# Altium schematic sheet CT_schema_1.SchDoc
size 515 x 464 mm
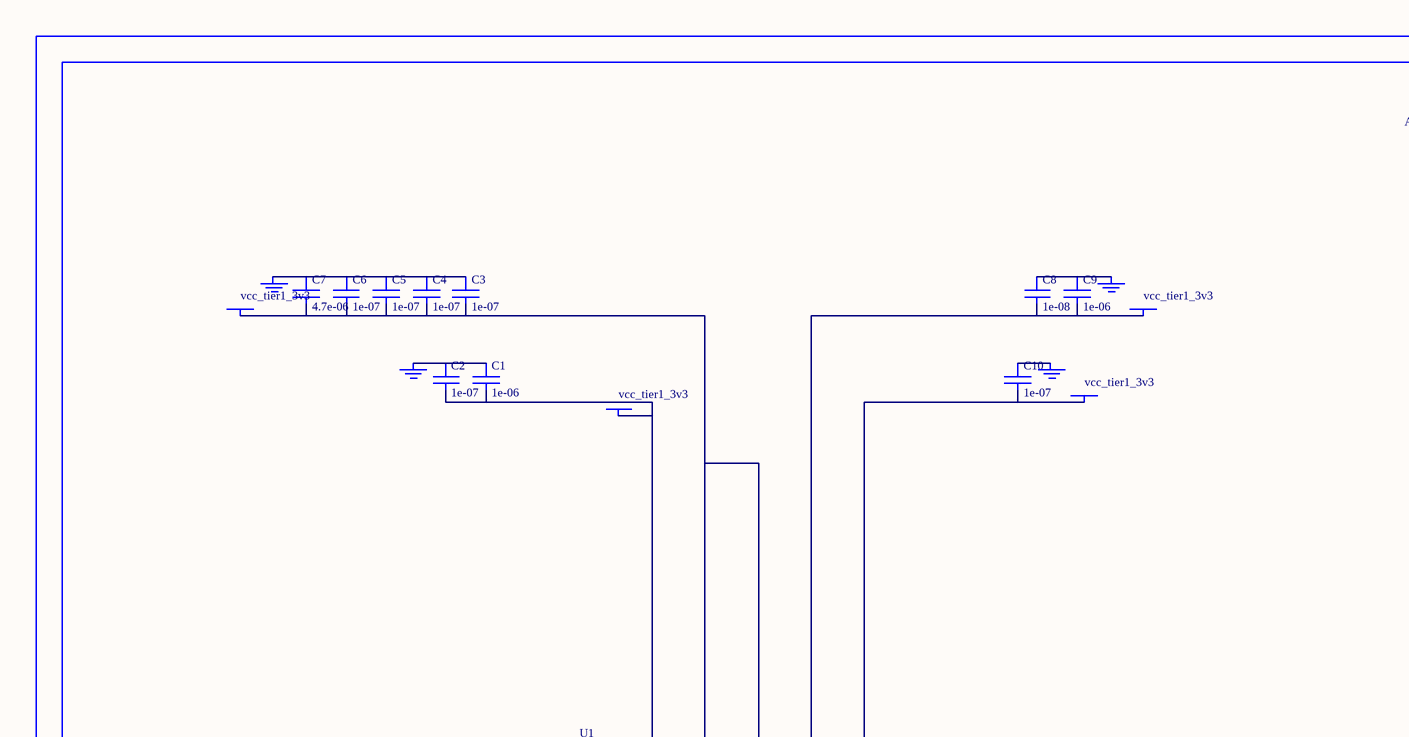
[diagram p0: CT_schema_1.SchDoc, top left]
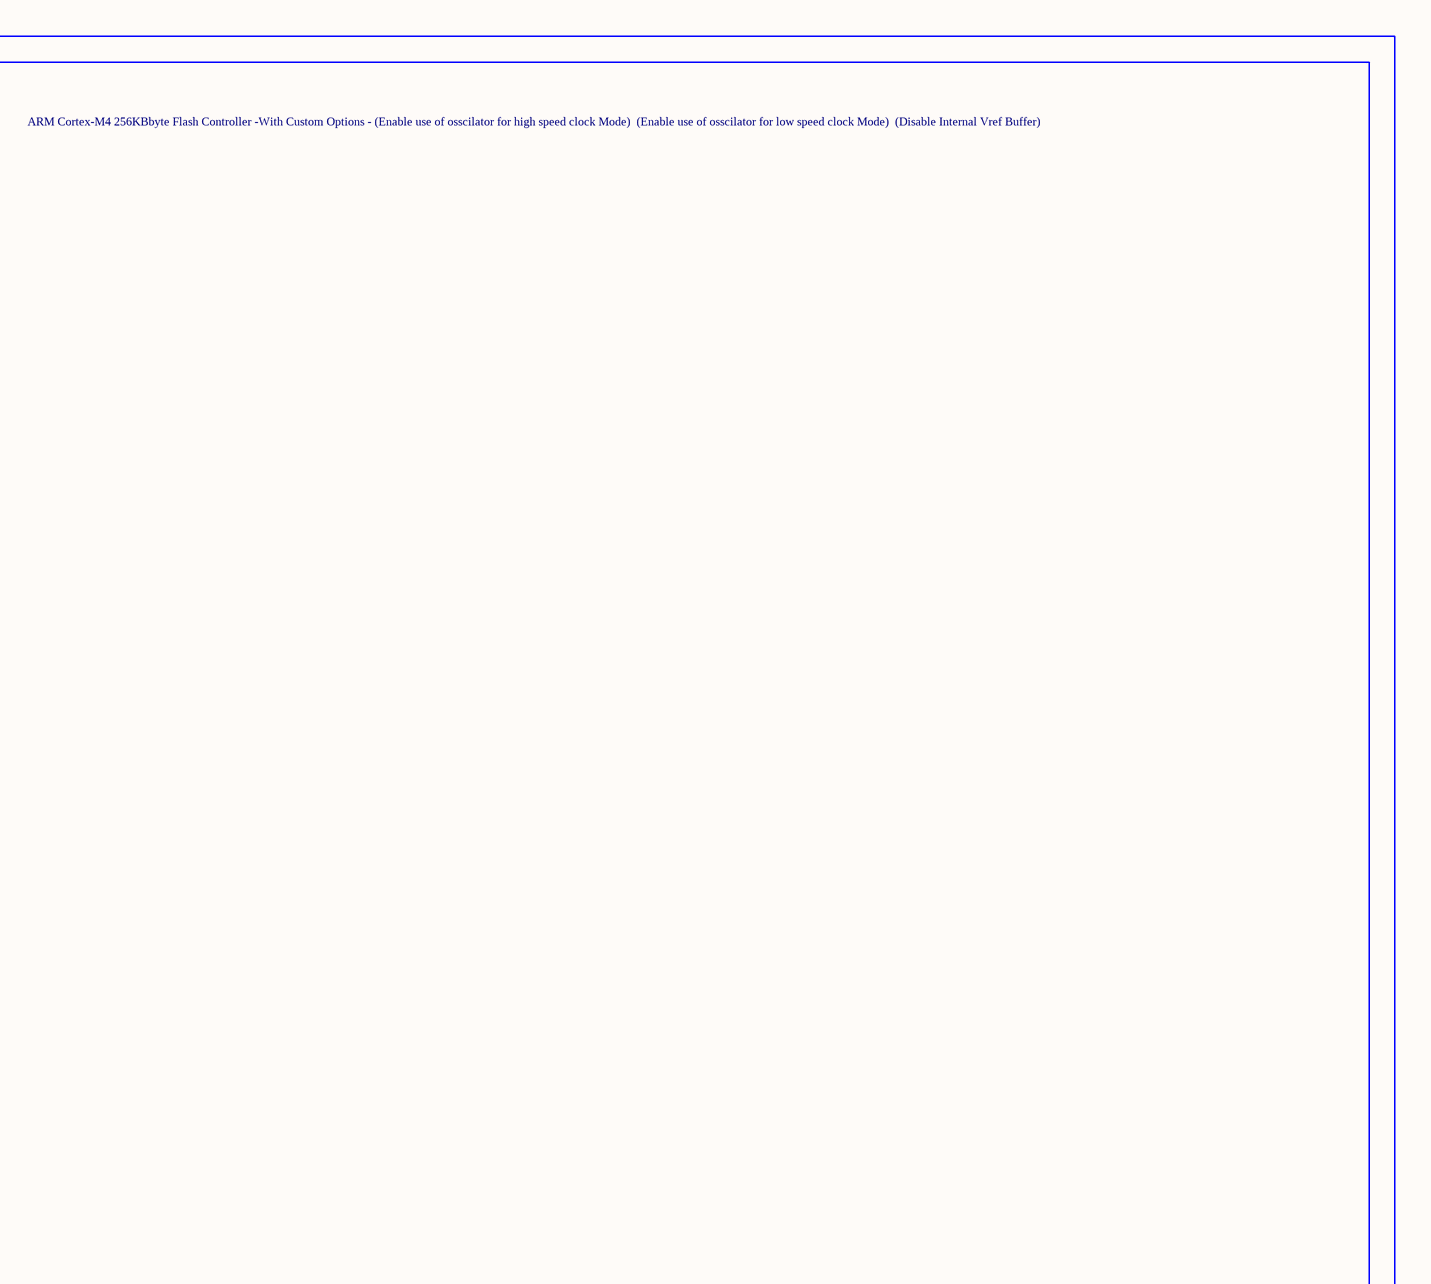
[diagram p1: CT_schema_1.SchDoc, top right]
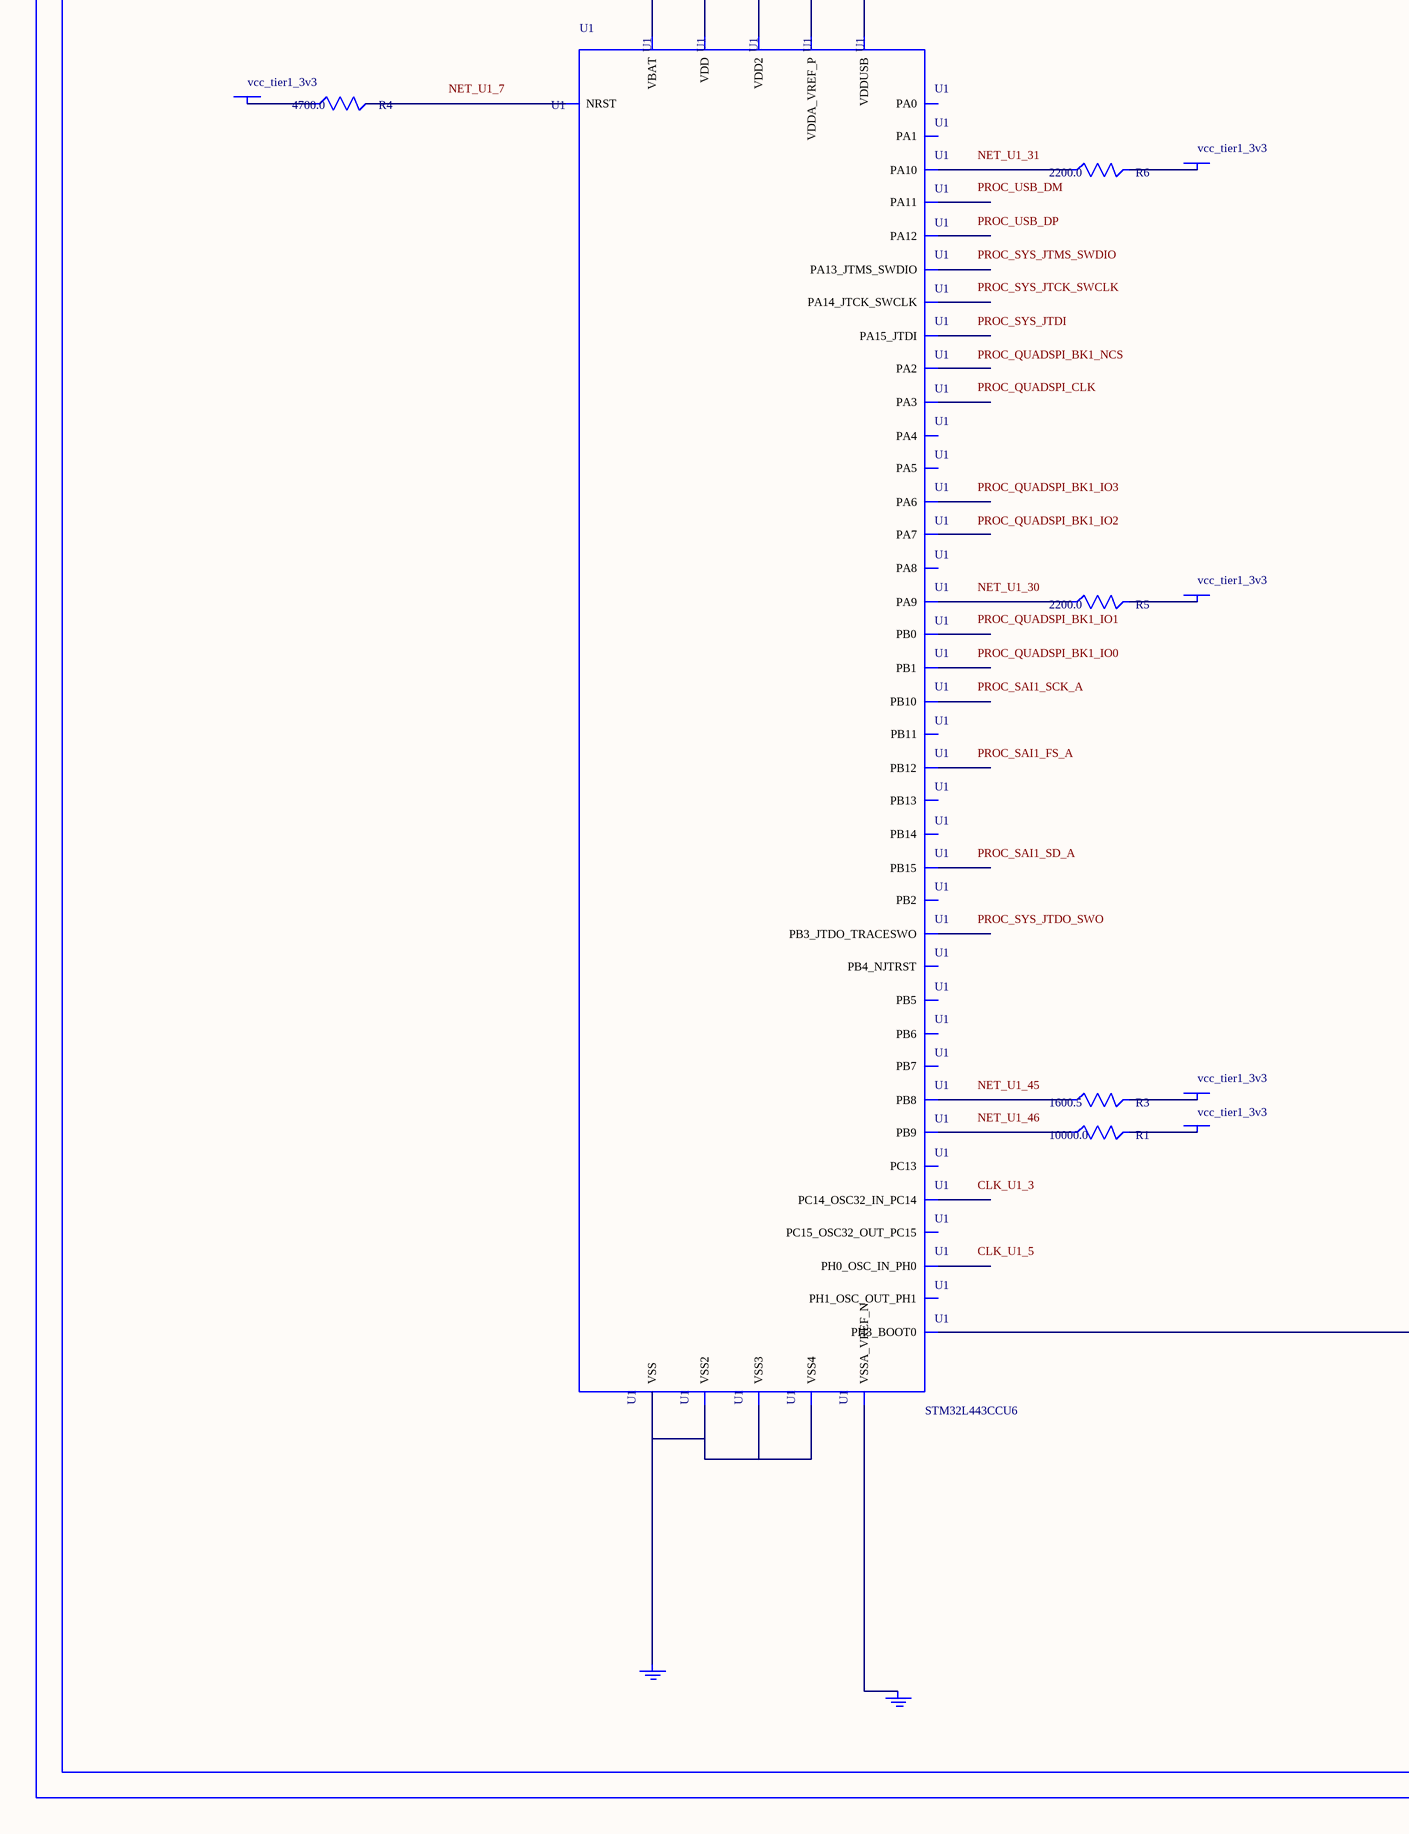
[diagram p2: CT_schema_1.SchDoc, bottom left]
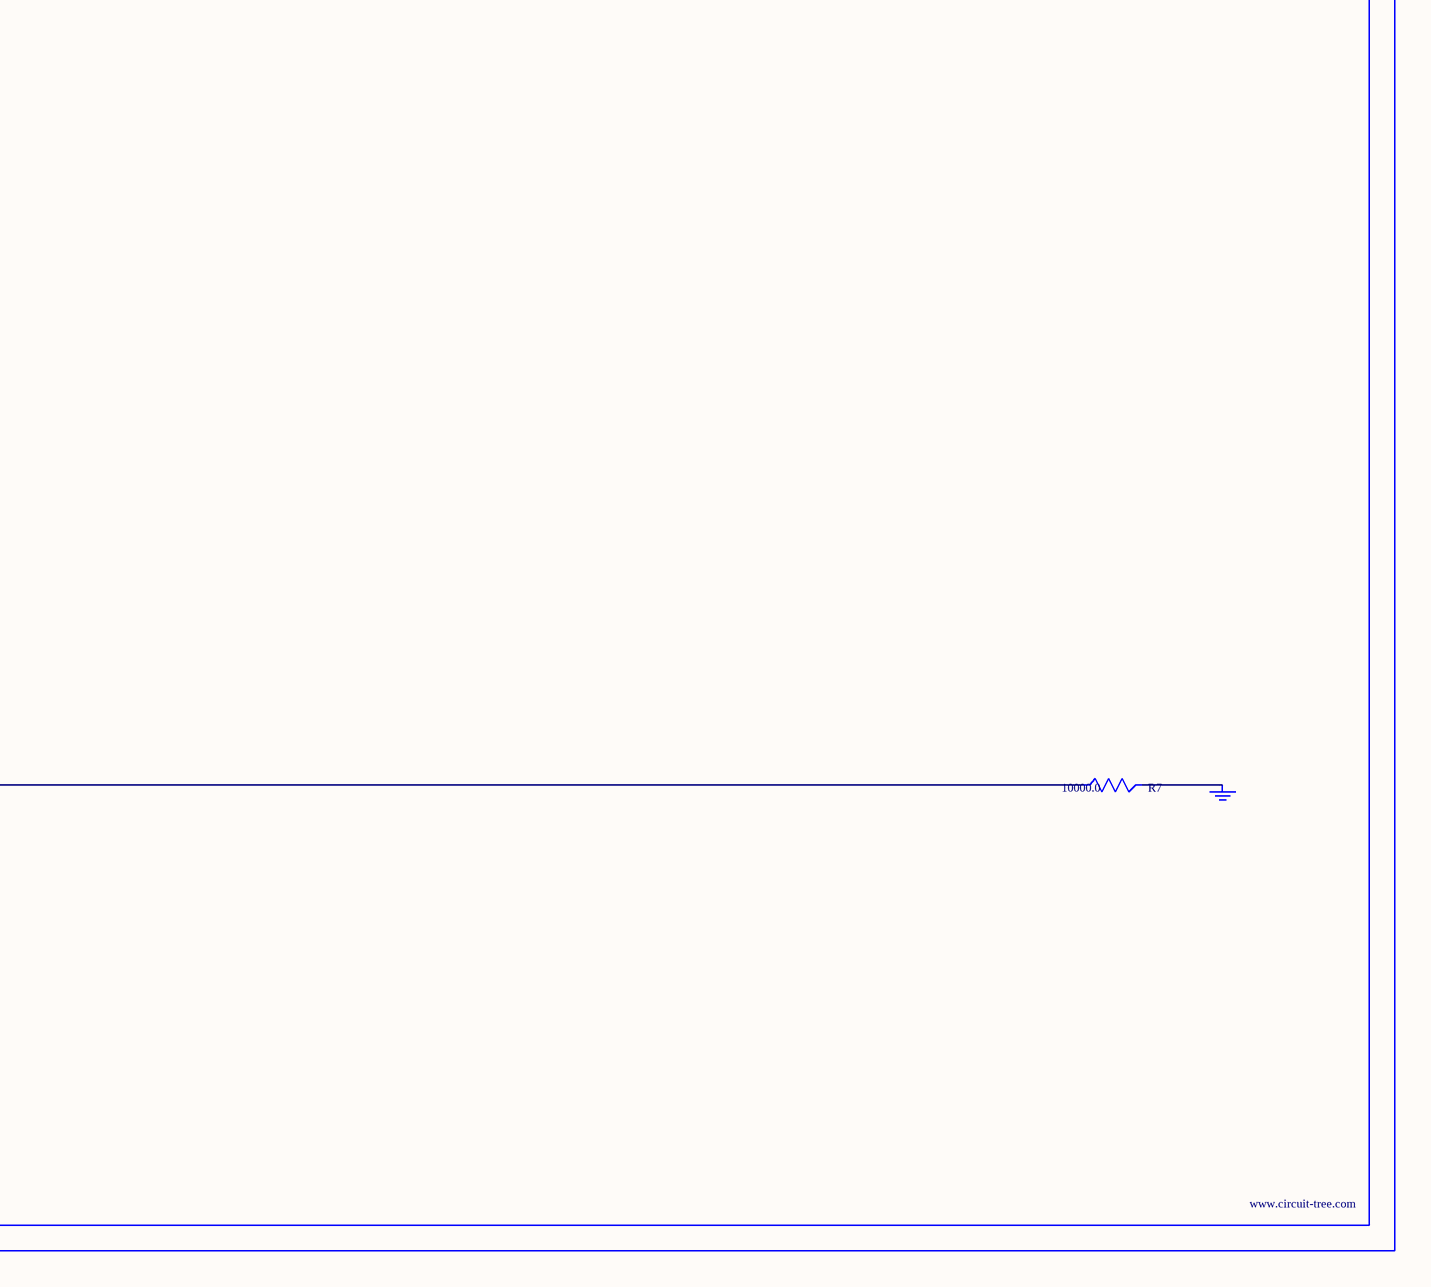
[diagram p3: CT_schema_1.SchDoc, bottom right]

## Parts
BORDER0  (no value)
C1  1e-06  [C0603]
C2  1e-07  [C0603]
C3  1e-07  [C0603]
C4  1e-07  [C0603]
C5  1e-07  [C0603]
C6  1e-07  [C0603]
C7  4.7e-06  [C0603]
C8  1e-08  [C0603]
C9  1e-06  [C0603]
C10  1e-07  [C0603]
GND_INSTANCE_0_0  (no value)
GND_INSTANCE_0_1  (no value)
GND_INSTANCE_0_2  (no value)
GND_INSTANCE_0_3  (no value)
GND_INSTANCE_0_4  (no value)
GND_INSTANCE_0_5  (no value)
GND_INSTANCE_0_6  (no value)
POWER_INSTANCE_0_0  vcc_tier1_3v3
POWER_INSTANCE_0_1  vcc_tier1_3v3
POWER_INSTANCE_0_2  vcc_tier1_3v3
POWER_INSTANCE_0_3  vcc_tier1_3v3
POWER_INSTANCE_0_4  vcc_tier1_3v3
POWER_INSTANCE_0_5  vcc_tier1_3v3
POWER_INSTANCE_0_6  vcc_tier1_3v3
POWER_INSTANCE_0_7  vcc_tier1_3v3
POWER_INSTANCE_0_8  vcc_tier1_3v3
R1  10000.0  [R0603]
R3  1600.5  [R0603]
R4  4700.0  [R0603]
R5  2200.0  [R0603]
R6  2200.0  [R0603]
R7  10000.0  [R0603]
U1  STM32L443CCU6  [UFQFPN48]

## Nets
NetC1_1: C1.1 C2.1 GND_INSTANCE_0_0.0(GND)
NetC1_2: C1.2 C2.2 POWER_INSTANCE_0_0.0(PWR) U1.1(VBAT)
NetC3_1: C3.1 C4.1 C5.1 C6.1 C7.1 GND_INSTANCE_0_3.0(GND)
NetC3_2: C3.2 C4.2 C5.2 C6.2 C7.2 POWER_INSTANCE_0_2.0(PWR) U1.24(VDD) U1.48(VDD2)
NetC8_1: C8.1 C9.1 GND_INSTANCE_0_2.0(GND)
NetC8_2: C8.2 C9.2 POWER_INSTANCE_0_1.0(PWR) U1.9(VDDA_VREF_P)
NetC10_1: C10.1 GND_INSTANCE_0_4.0(GND)
NetC10_2: C10.2 POWER_INSTANCE_0_3.0(PWR) U1.36(VDDUSB)
NetGND_INSTANCE_0_1_0: GND_INSTANCE_0_1.0(GND) U1.8(VSSA_VREF_N)
NetGND_INSTANCE_0_5_0: GND_INSTANCE_0_5.0(GND) R7.2
NetGND_INSTANCE_0_6_0: GND_INSTANCE_0_6.0(GND) U1.23(VSS) U1.35(VSS2) U1.47(VSS3) U1.49(VSS4)
NetPOWER_INSTANCE_0_4_0: POWER_INSTANCE_0_4.0(PWR) R4.1
NetPOWER_INSTANCE_0_5_0: POWER_INSTANCE_0_5.0(PWR) R5.2
NetPOWER_INSTANCE_0_6_0: POWER_INSTANCE_0_6.0(PWR) R6.2
NetPOWER_INSTANCE_0_7_0: POWER_INSTANCE_0_7.0(PWR) R3.2
NetPOWER_INSTANCE_0_8_0: POWER_INSTANCE_0_8.0(PWR) R1.2
NetR1_1: R1.1 U1.46(PB9)
NetR3_1: R3.1 U1.45(PB8)
NetR4_2: R4.2 U1.7(NRST)
NetR5_1: R5.1 U1.30(PA9)
NetR6_1: R6.1 U1.31(PA10)
NetR7_1: R7.1 U1.44(PH3_BOOT0)

Not connected (* = marked no-connect by the designer): U1 2(PC13) 3(PC14_OSC32_IN_PC14) 4(PC15_OSC32_OUT_PC15) 5(PH0_OSC_IN_PH0) 6(PH1_OSC_OUT_PH1) 10(PA0) 11(PA1) 12(PA2) 13(PA3) 14(PA4) 15(PA5) 16(PA6) 17(PA7) 18(PB0) 19(PB1) 20(PB2) 21(PB10) 22(PB11) 25(PB12) 26(PB13) 27(PB14) 28(PB15) 29(PA8) 32(PA11) 33(PA12) 34(PA13_JTMS_SWDIO) 37(PA14_JTCK_SWCLK) 38(PA15_JTDI) 39(PB3_JTDO_TRACESWO) 40(PB4_NJTRST) 41(PB5) 42(PB6) 43(PB7)

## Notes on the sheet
- Labels drawn without touching a wire or pin: CLK_U1_3, CLK_U1_5, NET_U1_7, NET_U1_30, NET_U1_31, NET_U1_45, NET_U1_46, PROC_QUADSPI_BK1_IO0, PROC_QUADSPI_BK1_IO1, PROC_QUADSPI_BK1_IO2, PROC_QUADSPI_BK1_IO3, PROC_QUADSPI_BK1_NCS, PROC_QUADSPI_CLK, PROC_SAI1_FS_A, PROC_SAI1_SCK_A, PROC_SAI1_SD_A, PROC_SYS_JTCK_SWCLK, PROC_SYS_JTDI, PROC_SYS_JTDO_SWO, PROC_SYS_JTMS_SWDIO, PROC_USB_DM, PROC_USB_DP

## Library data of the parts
BORDER0 = BORDER_PAGE0
C1 C9 = C0603C105K3RACTU
C2-C6 C10 = 06035C104K4Z2A
C7 = GRM188R6YA475KE15D
C8 = 06035C103K4Z2A
GND_INSTANCE_0_0-GND_INSTANCE_0_6 = GND
POWER_INSTANCE_0_0-POWER_INSTANCE_0_8 = PWR
R1 R7 = RC0603JR-0710KL
R3 = R3
R4 = RC0603JR-074K7L
R5 R6 = RC0603JR-072K2L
